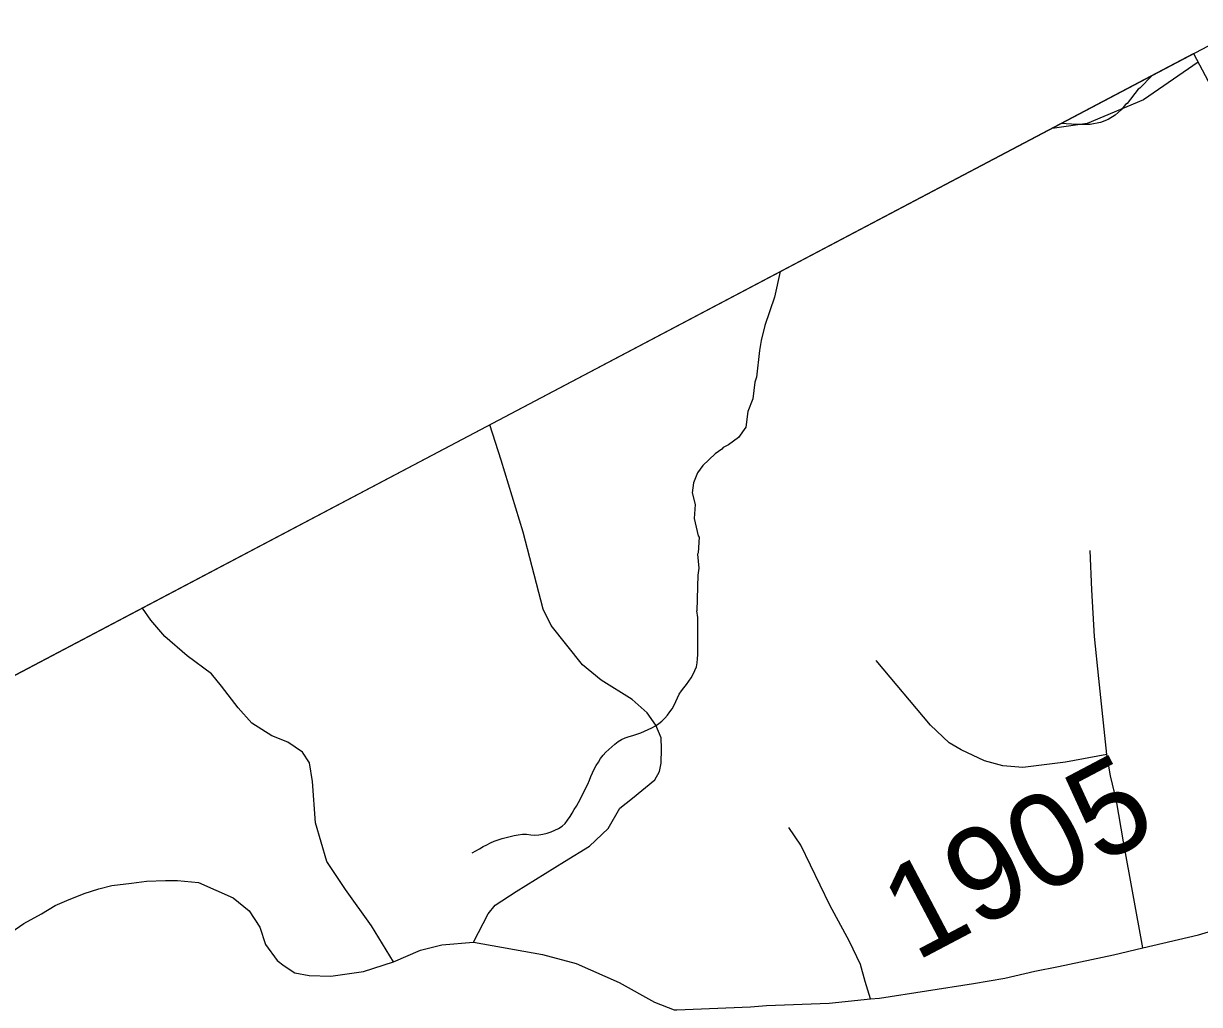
# Model space of a CAD drawing. Extents: x 1379448 to 1382868, y 593769 to 596827.
# Drawn here: x 1379976 to 1380162.2, y 595758 to 595913.3 of the extents above; entities that cross this region are included whole.
import ezdxf

# ---------------------------------------------------------------- set-up
doc = ezdxf.new("R2010")
doc.units = 0
for name, color, linetype in [('CTL Sheet Border CELL', 7, 'Continuous'), ('Old_Level_1', 7, 'Continuous'), ('Old_Level_32', 7, 'Continuous'), ('Old_Level_35', 7, 'Continuous'), ('Old_Level_59', 7, 'Continuous'), ('Old_Level_62', 7, 'Continuous'), ('Old_Level_8', 7, 'Continuous')]:
    doc.layers.add(name, color=color, linetype=linetype)

msp = doc.modelspace()

# ---------------------------------------------------------------- linework, layer by layer
at = {"layer": 'CTL Sheet Border CELL'}
msp.add_lwpolyline([(1381803.77, 596774.44), (1379496.12, 595557.87), (1380347.71, 593942.52), (1382655.37, 595159.09)], close=True, dxfattribs=at)
at = {"layer": 'Old_Level_1'}
for p, q in [((1379496.12, 595557.87), (1380161.32, 595908.56)), ((1380161.32, 595908.56), (1380447.79, 595365.17))]:
    msp.add_line(p, q, dxfattribs=at)
at = {"layer": 'Old_Level_32'}
for points in [[(1380147.59, 595797.61), (1380146.3, 595809.63), (1380145.63, 595816.3), (1380145.19, 595823.66), (1380144.96, 595829.92)], [(1380034.62, 595764.81), (1380031.13, 595770.46), (1380027, 595776.22), (1380024.05, 595780.65), (1380022.28, 595786.79), (1380021.8, 595793.31), (1380021.3, 595796.31), (1380020.19, 595797.98), (1380017.88, 595799.56), (1380015.34, 595800.55), (1380012.19, 595802.55), (1380010.04, 595805), (1380007.39, 595808.42), (1380005.8, 595810.38), (1380001.96, 595813.25), (1379998.42, 595816.29), (1379996.21, 595818.86), (1379994.87, 595820.8)], [(1380147.59, 595797.61), (1380141.04, 595796.38), (1380134.28, 595795.57), (1380131.11, 595795.8), (1380128.19, 595796.58), (1380124.53, 595798.35), (1380122.63, 595799.47), (1380119.65, 595802.23), (1380111.07, 595812.51)], [(1380153.3, 595766.99), (1380150.21, 595783.76), (1380149.08, 595790.25), (1380148.18, 595794.22), (1380147.59, 595797.61)], [(1379973.33, 595768.93), (1379976.07, 595770.85), (1379978.89, 595772.4), (1379981.03, 595773.69), (1379982.9, 595774.49), (1379985.62, 595775.62), (1379987.94, 595776.34), (1379990, 595776.89), (1379993.13, 595777.23), (1379995.53, 595777.58), (1379998.54, 595777.64), (1380000.4, 595777.68), (1380003.75, 595777.33), (1380009.23, 595774.91), (1380011.78, 595772.86), (1380013.43, 595770.29), (1380014.36, 595767.53), (1380016.19, 595764.97), (1380017.32, 595764.15), (1380018.97, 595763.03), (1380021.27, 595762.64), (1380024.7, 595762.54), (1380029.88, 595763.26), (1380034.62, 595764.81)], [(1380153.3, 595766.99), (1380162.08, 595769.07), (1380169.78, 595771.37), (1380178.26, 595772.53), (1380182.28, 595773.17), (1380185.83, 595773.88), (1380190.88, 595774.22), (1380198.39, 595773.84)], [(1380034.62, 595764.81), (1380038.89, 595766.64), (1380042.27, 595767.47), (1380047.28, 595767.89), (1380058.23, 595765.94), (1380063.55, 595764.52), (1380070.37, 595761.5), (1380075.96, 595758.38), (1380079.07, 595757.17), (1380079.47, 595757.16), (1380091.16, 595757.66), (1380093.69, 595757.86), (1380103.6, 595758.24), (1380110.14, 595758.91), (1380111.56, 595759.05), (1380126.48, 595761.37), (1380131.43, 595762.22), (1380136.18, 595763.33), (1380139.9, 595764.02), (1380148.64, 595765.89), (1380153.3, 595766.99)]]:
    msp.add_lwpolyline(points, dxfattribs=at)
at = {"layer": 'Old_Level_35'}
for points in [[(1380047.28, 595767.89), (1380049.6, 595772.39), (1380050.74, 595773.73), (1380054.06, 595775.91), (1380061.69, 595780.67), (1380065.65, 595783.07), (1380068.62, 595785.91), (1380070.44, 595789.09), (1380072.44, 595790.67), (1380076.01, 595793.61), (1380076.73, 595794.94), (1380077.02, 595796.26), (1380077.04, 595798.49), (1380076.98, 595800.26), (1380076.15, 595802.25), (1380074.8, 595804.18), (1380072.43, 595806.3), (1380067.49, 595809.35), (1380064.53, 595811.78), (1380059.57, 595818.03), (1380058.34, 595820.6), (1380055.13, 595832.79), (1380051.68, 595844.21), (1380049.87, 595849.8)], [(1380110.14, 595758.91), (1380109.31, 595761.67), (1380108.56, 595764.34), (1380106.85, 595767.99), (1380103.71, 595773.74), (1380099.12, 595783.27), (1380097.21, 595786.07)]]:
    msp.add_lwpolyline(points, dxfattribs=at)
at = {"layer": 'Old_Level_59'}
msp.add_lwpolyline([(1380162.04, 595907.19), (1380153.39, 595901.25), (1380144.47, 595897.51), (1380138.9, 595896.73)], dxfattribs=at)
at = {"layer": 'Old_Level_62'}
for points in [[(1380154.77, 595905.1), (1380152.8, 595903.09), (1380152.52, 595902.95), (1380150.8, 595900.66), (1380150.52, 595900.52), (1380149.87, 595899.66), (1380148.87, 595898.8), (1380147.76, 595898.16), (1380146.58, 595897.66), (1380144.93, 595897.37), (1380142.79, 595897.37), (1380140.33, 595897.49)], [(1380095.86, 595874.05), (1380094.95, 595870.01), (1380093.44, 595865.5), (1380092.84, 595863.15), (1380092.55, 595861.57), (1380092.08, 595857.32), (1380091.83, 595856.57), (1380091.54, 595853.93), (1380090.7, 595851.9), (1380090.4, 595849.43), (1380089.26, 595847.78), (1380087.68, 595846.64), (1380086.82, 595846.21), (1380086.61, 595845.93), (1380085.54, 595845.21), (1380083.6, 595843.35), (1380082.74, 595842.21), (1380082.1, 595840.64), (1380081.92, 595839.03), (1380082.38, 595837.2), (1380082.24, 595834.99), (1380082.86, 595832.24), (1380083.02, 595831.99), (1380082.87, 595829.53), (1380082.74, 595829.34), (1380082.95, 595827.13), (1380082.81, 595825.99), (1380082.67, 595820.37)], [(1380047.08, 595782.05), (1380047.65, 595782.37), (1380048.23, 595782.69), (1380048.8, 595783.02), (1380049.38, 595783.33), (1380049.96, 595783.62), (1380050.56, 595783.89), (1380051.18, 595784.11), (1380051.81, 595784.3), (1380052.45, 595784.46), (1380053.09, 595784.62), (1380053.73, 595784.76), (1380054.38, 595784.88), (1380055.02, 595784.97), (1380055.68, 595785), (1380056.34, 595784.91), (1380057, 595784.82), (1380057.64, 595784.87), (1380058.28, 595785), (1380058.93, 595785.17), (1380059.56, 595785.37), (1380060.18, 595785.62), (1380060.77, 595785.9), (1380061.31, 595786.24), (1380061.78, 595786.69), (1380062.19, 595787.22), (1380062.57, 595787.77), (1380062.92, 595788.33), (1380063.25, 595788.88), (1380063.58, 595789.45), (1380063.9, 595790.03), (1380064.21, 595790.61), (1380064.51, 595791.19), (1380064.8, 595791.77), (1380065.1, 595792.35), (1380065.39, 595792.93), (1380065.65, 595793.52), (1380065.89, 595794.12), (1380066.14, 595794.72), (1380066.41, 595795.31), (1380066.72, 595795.87), (1380067.06, 595796.42), (1380067.42, 595796.96), (1380067.8, 595797.48), (1380068.23, 595797.96), (1380068.69, 595798.4), (1380069.17, 595798.83), (1380069.66, 595799.24), (1380070.17, 595799.64), (1380070.71, 595799.97), (1380071.31, 595800.23), (1380071.92, 595800.44), (1380072.54, 595800.62), (1380073.16, 595800.82), (1380073.76, 595801.05), (1380074.36, 595801.29), (1380074.96, 595801.54), (1380075.55, 595801.82), (1380076.11, 595802.13), (1380076.63, 595802.49), (1380077.12, 595802.9), (1380077.57, 595803.36), (1380078, 595803.84), (1380078.4, 595804.34), (1380078.76, 595804.85), (1380079.06, 595805.42), (1380079.32, 595806.01), (1380079.58, 595806.59), (1380079.84, 595807.15), (1380080.22, 595807.67), (1380080.61, 595808.18), (1380081.01, 595808.69), (1380081.39, 595809.21), (1380081.75, 595809.75), (1380082.08, 595810.31), (1380082.36, 595810.89), (1380082.58, 595811.49), (1380082.72, 595812.12), (1380082.78, 595812.77), (1380082.79, 595813.42), (1380082.8, 595814.07), (1380082.81, 595814.72), (1380082.81, 595815.37), (1380082.81, 595816.02), (1380082.81, 595816.68), (1380082.81, 595817.33), (1380082.8, 595817.99), (1380082.8, 595818.64), (1380082.79, 595819.3), (1380082.67, 595820.37)]]:
    msp.add_lwpolyline(points, dxfattribs=at)

# ---------------------------------------------------------------- texts
at = {"layer": 'Old_Level_8'}
msp.add_text('1905', height=14.764, rotation=27.7977, dxfattribs=at).set_placement((1380117.28, 595764.75))

doc.saveas('drawing.dxf')
